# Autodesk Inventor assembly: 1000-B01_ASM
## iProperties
Created: 2007-03
Part Number: 1000-B01_ASM
Document SubType Name: Assembly
Designer: Andy Moles
Mass: 93.4604 g
Surface Area: 133.847 cm^2
Volume: 13.8792 cm^3
Density: 6.73383 g/cm^3
Author: Andy Moles
